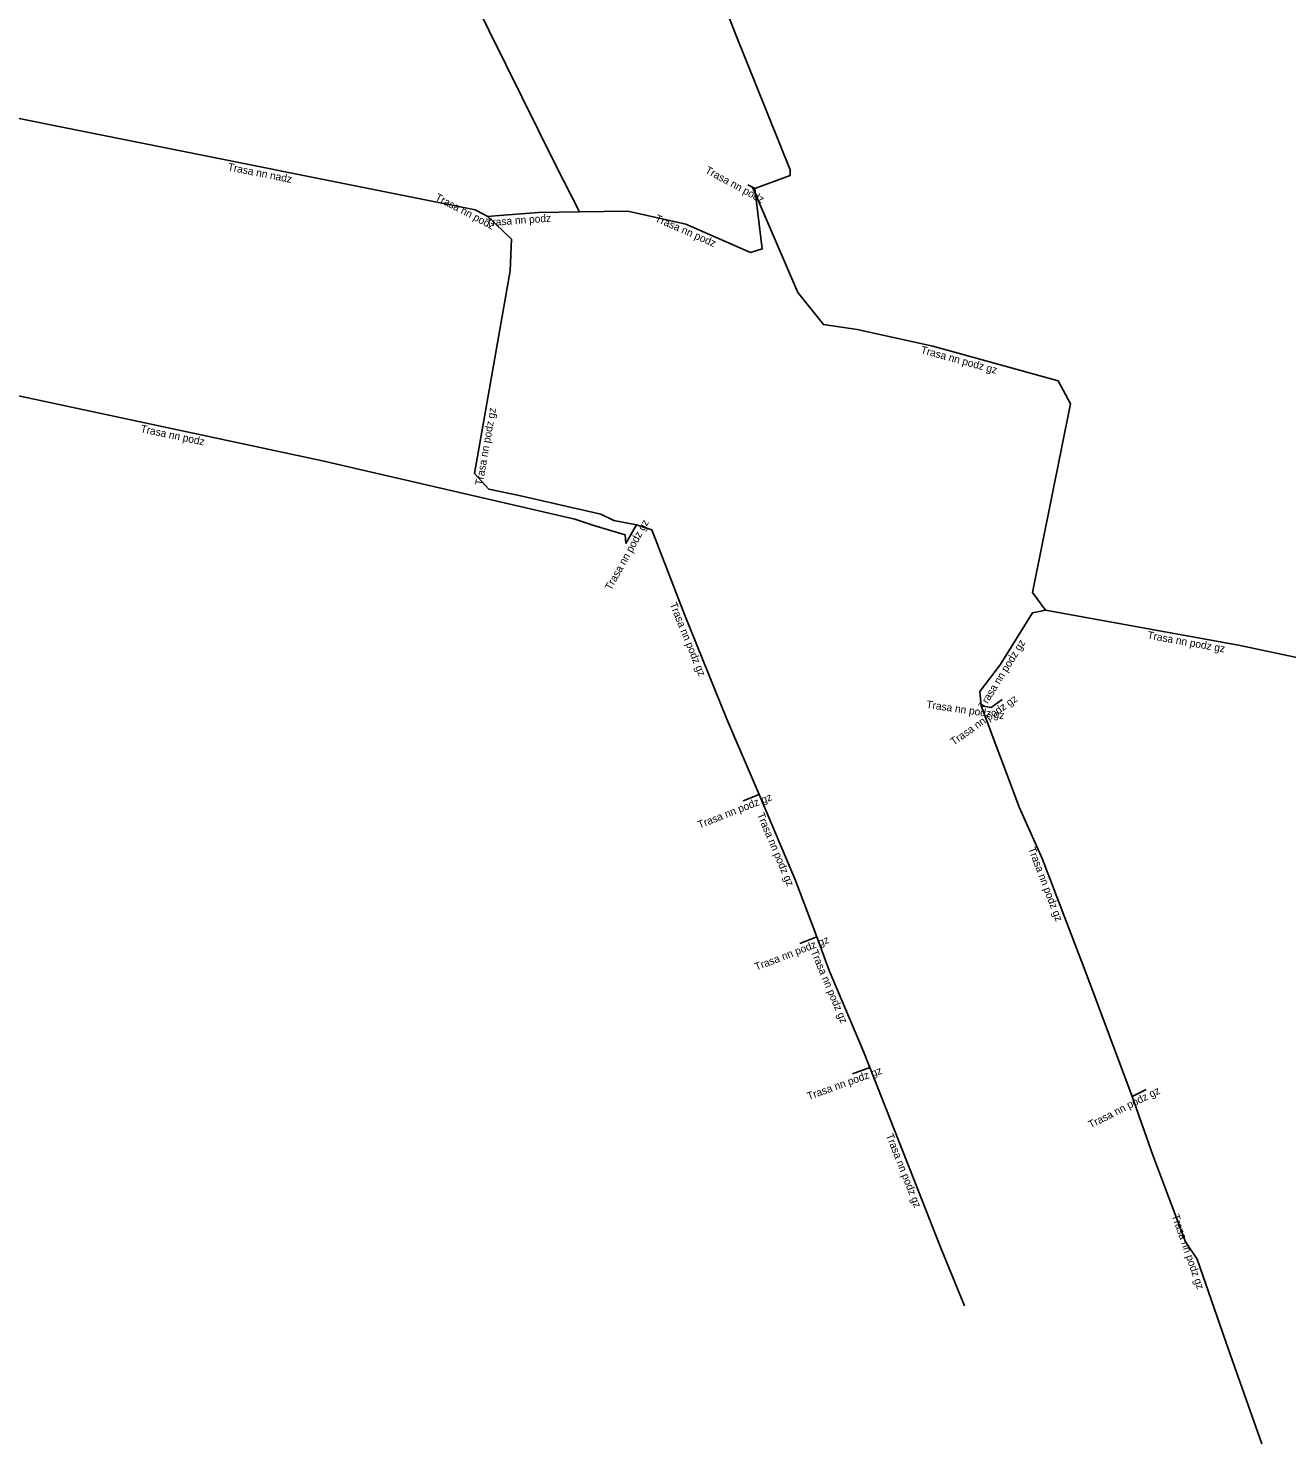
# Model space of a CAD drawing. Extents: x -684779 to -683642, y -1057424 to -1056854.
# Drawn here: x -684332.6 to -684250, y -1057050.2 to -1056957.3 of the extents above; entities that cross this region are included whole.
import ezdxf

# ---------------------------------------------------------------- set-up
doc = ezdxf.new("R2010")
doc.units = 0
doc.layers.add('Popiskový text - Ostatní atributy Trasy', color=7, linetype='Continuous')
doc.layers.add('Spojnice NN', color=7, linetype='Continuous')

msp = doc.modelspace()

# ---------------------------------------------------------------- linework, layer by layer
at = {"layer": 'Spojnice NN'}
for points in [[(-684284.9, -1056967.84), (-684282.58, -1056966.99), (-684282.58, -1056966.62), (-684286.14, -1056957.75), (-684294.76, -1056935.49), (-684303.42, -1056912.71), (-684305.5, -1056908.96), (-684310.33, -1056905.07), (-684312.97, -1056903.24), (-684320.44, -1056883.02), (-684325.97, -1056868.79), (-684327.31, -1056861.5), (-684327.87, -1056856.19), (-684328.16, -1056854.32)], [(-684311.01, -1056935.54), (-684303.42, -1056955.27), (-684297.98, -1056966.28), (-684296.41, -1056969.36)], [(-684329.357, -1056964.008), (-684352.25, -1056959.41)], [(-684303.24, -1056969.237), (-684329.357, -1056964.008)], [(-684296.41, -1056969.36), (-684293.23, -1056969.32), (-684289.43, -1056970.17), (-684285.17, -1056972.04), (-684284.41, -1056971.8), (-684284.9, -1056967.84)], [(-684285.36, -1056967.59), (-684285.05, -1056967.76), (-684282.07, -1056974.66), (-684280.39, -1056976.77), (-684278.18, -1056977.09), (-684273.21, -1056978.19), (-684264.99, -1056980.45), (-684264.18, -1056981.97), (-684266.67, -1056994.34), (-684265.83, -1056995.5)], [(-684285.36, -1056967.59), (-684284.9, -1056967.84)], [(-684302.421, -1056969.666), (-684300.86, -1056971.17), (-684300.94, -1056973.25), (-684303.28, -1056986.54), (-684302.35, -1056987.57), (-684300.36, -1056987.97), (-684294.99, -1056989.2), (-684294.15, -1056989.62), (-684292.67, -1056989.91)], [(-684302.421, -1056969.666), (-684303.24, -1056969.237)], [(-684296.41, -1056969.36), (-684299.09, -1056969.42), (-684301.94, -1056969.63), (-684302.421, -1056969.666)], [(-684351.32, -1056977.5), (-684340.8, -1056979.83), (-684313.27, -1056985.7), (-684296.71, -1056989.53), (-684295.46, -1056989.94), (-684293.4, -1056990.57), (-684293.349, -1056991.134)], [(-684292.67, -1056989.91), (-684293.349, -1056991.134)], [(-684292.67, -1056989.91), (-684291.66, -1056990.24), (-684289.52, -1056995.79), (-684286.73, -1057002.65), (-684284.61, -1057007.6)], [(-684265.83, -1056995.5), (-684266.68, -1056995.68), (-684268.79, -1056999.09), (-684270.14, -1057000.83), (-684270.04, -1057001.79)], [(-684265.83, -1056995.5), (-684253.16, -1056997.79), (-684245.31, -1056999.47), (-684244.68, -1056999.68)], [(-684269.396, -1057001.885), (-684268.664, -1057001.372)], [(-684270.04, -1057001.79), (-684269.396, -1057001.885)], [(-684270.04, -1057001.79), (-684267.52, -1057008.47), (-684266.03, -1057011.79), (-684263.1, -1057019.46), (-684260.14, -1057027.41)], [(-684284.61, -1057007.6), (-684285.668, -1057008.016)], [(-684284.61, -1057007.6), (-684282.23, -1057013.23), (-684280.837, -1057016.944)], [(-684281.951, -1057017.371), (-684280.837, -1057016.944)], [(-684280.837, -1057016.944), (-684280.01, -1057019.15), (-684277.77, -1057024.45), (-684277.353, -1057025.509)], [(-684278.489, -1057025.92), (-684277.353, -1057025.509)], [(-684277.353, -1057025.509), (-684274.64, -1057032.4), (-684272.71, -1057037.29), (-684271.131, -1057041.146)], [(-684260.14, -1057027.41), (-684259.217, -1057026.942)], [(-684251.63, -1057050.19), (-684253.82, -1057044), (-684255.87, -1057038.08), (-684256.64, -1057036.95), (-684258.77, -1057031.25), (-684260.14, -1057027.41)]]:
    msp.add_lwpolyline(points, dxfattribs=at)

# ---------------------------------------------------------------- texts
at = {"layer": 'Popiskový text - Ostatní atributy Trasy'}
for s, rotation, p in [('Trasa nn nadz', 348.67826, (-684319.512, -1056966.642)), ('Trasa nn podz', 331.47688, (-684288.206, -1056966.783)), ('Trasa nn podz', 332.35402, (-684305.92, -1056968.567)), ('Trasa nn podz', 4.21418, (-684302.51, -1056970.324)), ('Trasa nn podz', 336.3001, (-684291.491, -1056969.976)), ('Trasa nn podz gz', 344.62699, (-684274.048, -1056978.634)), ('Trasa nn podz gz', 80.01416, (-684302.763, -1056987.351)), ('Trasa nn podz', 347.96353, (-684325.233, -1056983.814)), ('Trasa nn podz gz', 60.98118, (-684294.33, -1056994.242)), ('Trasa nn podz gz', 292.13185, (-684290.5, -1056995.105)), ('Trasa nn podz gz', 349.75486, (-684259.166, -1056997.365)), ('Trasa nn podz gz', 58.25209, (-684269.836, -1057002.016)), ('Trasa nn podz gz', 351.6085, (-684273.664, -1057001.912)), ('Trasa nn podz gz', 35.03665, (-684271.845, -1057004.396)), ('Trasa nn podz gz', 21.46449, (-684288.525, -1057009.837)), ('Trasa nn podz gz', 292.9155, (-684284.762, -1057008.909)), ('Trasa nn podz gz', 290.90725, (-684266.971, -1057011.148)), ('Trasa nn podz gz', 20.972, (-684284.797, -1057019.158)), ('Trasa nn podz gz', 292.91094, (-684281.241, -1057017.906)), ('Trasa nn podz gz', 19.88991, (-684281.361, -1057027.651)), ('Trasa nn podz gz', 26.88693, (-684262.858, -1057029.517)), ('Trasa nn podz gz', 291.53831, (-684276.304, -1057029.955)), ('Trasa nn podz gz', 289.10014, (-684257.545, -1057035.228))]:
    msp.add_text(s, height=0.5, rotation=rotation, dxfattribs=at).set_placement(p)

doc.saveas('drawing.dxf')
